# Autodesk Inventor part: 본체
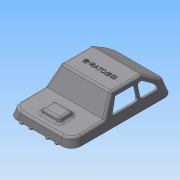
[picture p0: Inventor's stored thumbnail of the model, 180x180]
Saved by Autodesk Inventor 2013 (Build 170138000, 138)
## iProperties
Created: 2015-05
Part Number: 본체
Material: 일반
Document SubType Name: Modeling
Designer: dgall
Density: 1 g/cm^3
Author: dgall
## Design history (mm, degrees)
sketch "스케치1"
  geometry: L1 (-61, 0)-(-58.588, 9); L2 (-58.588, 9)-(-19, 10); L3 (-19, 10)-(-5.736, 30); L4 (-5.736, 30)-(31, 30); L5 (31, 30)-(61, 10); L6 (61, 10)-(61, 0); L7 (61, 0)-(-61, 0); 2 further points
  constraints: 14 end point, 1 coincident, 1 horizontal, 1 midpoint, 1 parallel, 1 vertical
  dimensions: "d0" = 122 distance of L6.end L1.start; "d1" = 9 vertical distance of L1.start L1.end; "d2" = 42 horizontal distance of L2.end L1.start; "d3" = 105 deg angle of L1 L7; "d4" = 30 distance between parallel lines of L7 L4; "d7" = 125 deg angle of L3 L2; "d8" = 20 vertical distance of L2.end L3.end; "d29" = 30 horizontal distance of L6.end L4.end; "d30" = 20 vertical distance of L5.end L4.end
extrude "돌출1" new body sketch "스케치1" stored distance "d10" = 76; taper "d11" = 0 deg
node "작업 평면1"
sketch "스케치2"
  geometry: L1 (38, 10)-(38, 30) reference; L2 (38, 9)-(38, 10) reference; L3 (38, 0)-(38, 9) reference; L4 (38, 0)-(-38, 0) reference; L5 (-38, 30)-(38, 30) reference; L6 (38, 0)-(29.962, 30); L7 (38, 0)-(38, 30); L8 (29.962, 30)-(38, 30); 1 further point
  constraints: 6 end point, 1 collinear, 1 perpendicular, 1 point on line
  dimensions: "d13" = 105 deg angle of L4 L6
extrude "돌출2" cut sketch "스케치2" distance "d14" = 150; taper "d15" = 0 deg
node "작업 평면2"
sketch "스케치4"
  geometry: L1 (61, 10)-(61, 0) reference; L2 (-61, 0)-(61, 0) reference; L3 (31, 30)-(61, 10) reference; L4 (61, 0)-(57.738, 12.175); L5 (57.738, 12.175)-(61, 10); L6 (61, 0)-(61, 10); 1 further point
  constraints: 6 end point, 1 collinear, 1 perpendicular, 1 point on line
  dimensions: "d32" = 105 deg angle of L4 L2
extrude "돌출3" cut sketch "스케치4" distance "d33" = 150; taper "d34" = 0 deg
feature "쉘2" dims "d35" = 2
sketch "스케치6"
  geometry: L1 (-5.736, 30)-(31, 30) reference; L2 (-19, 10)-(-5.736, 30) reference; L3 (31, 30)-(57.738, 12.175) reference; L4 (61, 0)-(57.738, 12.175) reference; L5 (-3.052, 25)-(-13, 10); L6 (-3.052, 25)-(21, 25); L7 (21, 25)-(21, 10); L8 (21, 10)-(-13, 10); L9 (29.486, 25)-(51.986, 10); L10 (29.486, 25)-(23.986, 25); L11 (23.986, 25)-(23.986, 10); L12 (23.986, 10)-(51.986, 10); 1 further point
  constraints: 16 end point, 6 parallel, 2 perpendicular
  dimensions: "d46" = 5 distance between parallel lines of L2 L5; "d48" = 5 distance between parallel lines of L1 L6; "d49" = 34 distance of L7.end L5.end; "d50" = 15 distance of L6.end L7.end; "d51" = 5 distance between parallel lines of L3 L9; "d52" = 5 distance from line of L1 L9.start; "d53" = 15 vertical distance of L9.start L9.end; "d54" = 28 distance of L11.end L9.end
extrude "돌출4" cut sketch "스케치6" distance "d55" = 150; taper "d56" = 0 deg
sketch "스케치8"
  geometry: L1 (0, 0)-(68.087, 0) reference; L2 (21.044, 26.867)-(47.044, 26.867); L3 (47.044, 26.867)-(47.044, 6.867); L4 (47.044, 6.867)-(21.044, 6.867); L5 (21.044, 6.867)-(21.044, 26.867); L6 (72.044, -4.133)-(-3.956, -4.133) reference; 3 further points
  constraints: 8 end point, 2 midpoint, 2 parallel, 1 horizontal, 1 perpendicular, 1 vertical alignment
  dimensions: "d63" = 26 distance of L2.start L2.end; "d65" = 20 distance of L2.end L3.end; "d66" = 11 distance between parallel lines of L4 L6
extrude "돌출6" join sketch "스케치8" distance "d67" = 7; taper "d68" = -20 deg
sketch "스케치9"
  geometry: L1 (21.044, 26.867)-(47.044, 26.867) reference; L2 (21.044, 6.867)-(21.044, 26.867) reference; L3 (47.044, 6.867)-(21.044, 6.867) reference; L4 (47.044, 26.867)-(47.044, 6.867) reference; L5 (45.044, 24.867)-(23.044, 24.867); L6 (23.044, 24.867)-(23.044, 8.867); L7 (23.044, 8.867)-(45.044, 8.867); L8 (45.044, 8.867)-(45.044, 24.867); 1 further point
  constraints: 8 end point, 3 other
  dimensions: "d69" = 2 distance between parallel lines of L1 L5
extrude "돌출7" cut sketch "스케치9" distance "d70" = 5; taper "d71" = -20 deg
fillet "모깎기1" dims "d72" = 12
fillet "모깎기2" dims "d73" = 12
fillet "모깎기3" dims "d74" = 3
fillet "모깎기4" dims "d75" = 3
fillet "모깎기5" dims "d76" = 3
fillet "모깎기6" dims "d77" = 3
sketch "스케치10"
  geometry: L1 (2.071, 119.929)-(50.747, 119.929) reference; L2 (62.338, 108.338)-(62.338, 13.662) reference; L3 (50.747, 2.071)-(2.071, 2.071) reference; L4 (-9.521, 13.662)-(-9.521, 108.338) reference; L5 (50.747, 120.929)-(2.071, 120.929); L6 (-10.521, 108.338)-(-10.521, 13.662); L7 (2.071, 1.071)-(50.747, 1.071); L8 (63.338, 13.662)-(63.338, 108.338); 5 further points; 4 other entities
  constraints: 8 end point, 7 parallel, 16 other
  dimensions: "d78" = 1 distance between parallel lines of L5 L1
extrude "돌출8" join sketch "스케치10" distance "d79" = 1; taper "d80" = 0 deg
fillet "모깎기7" dims "d81" = 3
sketch "스케치11"
  geometry: L1 (0, 122)-(52.818, 122) reference; C1 r 3 at (26.409, 21); 1 further point
  constraints: 1 centre point, 1 vertical alignment
  dimensions: "d82" = 6 diameter of C1; "d84" = 101 distance from line of L1 C1.centre
extrude "돌출9" join sketch "스케치11" stored distance "d85" = 1; taper "d86" = 2 deg
sketch "스케치12"
  geometry: L1 (-28.863, 9.751)-(-19, 10) reference; L2 (-19, 10)-(-6.626, 28.658) reference; L3 (-4.125, 30)-(30.092, 30) reference; L4 (31.756, 29.496)-(56.797, 12.802) reference; L5 (58.03, 11.082)-(61, 0) reference; L6 (61, 0)-(59.929, 0) reference; L7 (59.929, 0)-(59.929, -1) reference; L8 (59.929, -1)-(58.929, -1) reference; L9 (58.929, -1)-(58.929, 0) reference; L10 (58.929, 0)-(56.294, 9.837) reference; L11 (55.06, 11.556)-(31.15, 27.496) reference; L12 (29.486, 28)-(-3.052, 28) reference; L13 (-5.552, 26.658)-(-17.046, 9.328) reference; L14 (-19.47, 7.987)-(-30.084, 7.719) reference; L15 (-32.952, 9.621)-(-33.362, 10.664) reference; L16 (-36.23, 12.566)-(-36.561, 12.557) reference; L17 (-36.561, 12.557)-(-37, 0) reference; L18 (-37, 0)-(-43, 0) reference; L19 (-43, 0)-(-43.432, 12.384) reference; L20 (-43.432, 12.384)-(-44.386, 12.36) reference; L21 (-47.155, 10.315)-(-47.511, 9.254) reference; L22 (-50.279, 7.209)-(-54.802, 7.095) reference; L23 (-57.624, 4.872)-(-58.929, 0) reference; L24 (-58.929, 0)-(-58.929, -1) reference; L25 (-58.929, -1)-(-59.929, -1) reference; L26 (-59.929, -1)-(-59.929, 0) reference; L27 (-59.929, 0)-(-61, 0) reference; L28 (-61, 0)-(-59.169, 6.834) reference; L29 (-56.347, 9.057)-(-51.601, 9.176) reference; L30 (-48.833, 11.221)-(-48.477, 12.282) reference; L31 (-45.708, 14.327)-(-35.009, 14.597) reference; L32 (-32.141, 12.695)-(-31.731, 11.653) reference; L33 (-42.07, 2)-(-42.07, 12.919); L34 (-46.925, 12.919)-(-45, 2); L35 (47.338, 0)-(-47.338, 0) reference; L36 (-37, 0)-(-43, 0) reference; L37 (-45, 2)-(-42.07, 2); L38 (-42.07, 12.919)-(-46.925, 12.919); A1 r 3 centre (-28.939, 12.75) between (-31.731, 11.653) and (-28.863, 9.751) reference; A2 r 3 centre (-4.125, 27) between (-4.125, 30) and (-6.626, 28.658) reference; A3 r 3 centre (30.092, 27) between (31.756, 29.496) and (30.092, 30) reference; A4 r 3 centre (55.133, 10.306) between (58.03, 11.082) and (56.797, 12.802) reference; A5 r 3 centre (53.396, 9.06) between (56.294, 9.837) and (55.06, 11.556) reference; A6 r 3 centre (29.486, 25) between (31.15, 27.496) and (29.486, 28) reference; A7 r 3 centre (-3.052, 25) between (-3.052, 28) and (-5.552, 26.658) reference; A8 r 3 centre (-19.546, 10.987) between (-19.47, 7.987) and (-17.046, 9.328) reference; A9 r 3 centre (-30.16, 10.718) between (-32.952, 9.621) and (-30.084, 7.719) reference; A10 r 3 centre (-36.154, 9.567) between (-33.362, 10.664) and (-36.23, 12.566) reference; A11 r 3 centre (-44.311, 9.361) between (-44.386, 12.36) and (-47.155, 10.315) reference; A12 r 3 centre (-50.355, 10.208) between (-50.279, 7.209) and (-47.511, 9.254) reference; A13 r 3 centre (-54.726, 4.096) between (-54.802, 7.095) and (-57.624, 4.872) reference; A14 r 3 centre (-56.271, 6.058) between (-56.347, 9.057) and (-59.169, 6.834) reference; A15 r 3 centre (-51.677, 12.176) between (-51.601, 9.176) and (-48.833, 11.221) reference; A16 r 3 centre (-45.633, 11.328) between (-45.708, 14.327) and (-48.477, 12.282) reference; A17 r 3 centre (-34.933, 11.598) between (-32.141, 12.695) and (-35.009, 14.597) reference; 3 further points
  constraints: 8 end point, 2 parallel, 1 midpoint, 1 perpendicular, 1 point on circle, 1 point on line
  dimensions: "d90" = 10 deg angle of L33 L34; "d110" = 5 horizontal distance of point (-40, 0) L34.end; "d112" = 2.06984 distance from line of point (-40, 0) L33; "d114" = 2 distance between parallel lines of L35 L37; "d115" = 12.91909 distance between parallel lines of L36 L38
extrude "돌출10" join sketch "스케치12" stored distance "d92" = 2; taper "d93" = 0 deg
node "작업 평면3"
hole "구멍1" diameter "d97" = 3.242; stored, may be unused: countersink angle "d101" = 90 deg, drill point angle "d103" = 118 deg; dims "d95" = 10, "d96" = 10, "d98" = 9, "d99" = 4, "d100" = 2, "d102" = 11
sketch "스케치13"
  geometry: C1 r 3 at (26.409, 101); C2 r 1.621 at (26.409, 21) reference; 1 further point
  constraints: 1 centre point, 1 vertical alignment
  dimensions: "d104" = 6 diameter of C1; "d106" = 80 distance of C1.centre C2.centre
extrude "돌출11" join sketch "스케치13" stored distance "d107" = 2; taper "d108" = 2 deg
sketch "스케치14"
  geometry: L1 (-28.863, 9.751)-(-19, 10) reference; L2 (-19, 10)-(-6.626, 28.658) reference; L3 (-4.125, 30)-(30.092, 30) reference; L4 (31.756, 29.496)-(56.797, 12.802) reference; L5 (58.03, 11.082)-(61, 0) reference; L6 (61, 0)-(59.929, 0) reference; L7 (59.929, 0)-(59.929, -1) reference; L8 (59.929, -1)-(58.929, -1) reference; L9 (58.929, -1)-(58.929, 0) reference; L10 (58.929, 0)-(56.294, 9.837) reference; L11 (55.06, 11.556)-(43.669, 19.15) reference; L12 (43.669, 19.15)-(43, 0) reference; L13 (43, 0)-(37, 0) reference; L14 (37, 0)-(36.156, 24.159) reference; L15 (36.156, 24.159)-(31.15, 27.496) reference; L16 (29.486, 28)-(-3.052, 28) reference; L17 (-5.552, 26.658)-(-17.046, 9.328) reference; L18 (-19.47, 7.987)-(-30.084, 7.719) reference; L19 (-32.952, 9.621)-(-33.362, 10.664) reference; L20 (-33.44, 10.845)-(-35, 2) reference; L21 (-36.93, 2)-(-37, 0) reference; L22 (-37, 0)-(-38.379, 0) reference; L23 (-38.379, 0)-(-38.379, 11) reference; L24 (-38.379, 11)-(-40, 11.974) reference; L25 (-40, 11.974)-(-41.621, 11) reference; L26 (-41.621, 11)-(-41.621, 0) reference; L27 (-41.621, 0)-(-43, 0) reference; L28 (-43, 0)-(-43.07, 2) reference; L29 (-45, 2)-(-46.633, 11.26) reference; L30 (-47.155, 10.315)-(-47.511, 9.254) reference; L31 (-50.279, 7.209)-(-54.802, 7.095) reference; L32 (-57.624, 4.872)-(-58.929, 0) reference; L33 (-58.929, 0)-(-58.929, -1) reference; L34 (-58.929, -1)-(-59.929, -1) reference; L35 (-59.929, -1)-(-59.929, 0) reference; L36 (-59.929, 0)-(-61, 0) reference; L37 (-61, 0)-(-59.169, 6.834) reference; L38 (-56.347, 9.057)-(-51.601, 9.176) reference; L39 (-48.833, 11.221)-(-48.477, 12.282) reference; L40 (-45.708, 14.327)-(-35.009, 14.597) reference; L41 (-32.141, 12.695)-(-31.731, 11.653) reference; L42 (-35, 2)-(-36.93, 2) reference; L43 (-43.07, 2)-(-45, 2) reference; L44 (43, 0)-(46.092, 17.535); L45 (37, 0)-(32.285, 26.74); L46 (40, 0)-(40, 24); L47 (37, 0)-(38.023, 0); L48 (38.023, 0)-(38.023, 23.037); L49 (38.023, 23.037)-(36.156, 24.159); L50 (43, 0)-(42.333, 0); L51 (42.333, 0)-(42.333, 19.953); L52 (42.333, 19.953)-(43.669, 19.15); A1 r 3 centre (-28.939, 12.75) between (-31.731, 11.653) and (-28.863, 9.751) reference; A2 r 3 centre (-4.125, 27) between (-4.125, 30) and (-6.626, 28.658) reference; A3 r 3 centre (30.092, 27) between (31.756, 29.496) and (30.092, 30) reference; A4 r 3 centre (55.133, 10.306) between (58.03, 11.082) and (56.797, 12.802) reference; A5 r 3 centre (53.396, 9.06) between (56.294, 9.837) and (55.06, 11.556) reference; A6 r 3 centre (29.486, 25) between (31.15, 27.496) and (29.486, 28) reference; A7 r 3 centre (-3.052, 25) between (-3.052, 28) and (-5.552, 26.658) reference; A8 r 3 centre (-19.546, 10.987) between (-19.47, 7.987) and (-17.046, 9.328) reference; A9 r 3 centre (-30.16, 10.718) between (-32.952, 9.621) and (-30.084, 7.719) reference; A10 r 3 centre (-36.154, 9.567) between (-33.362, 10.664) and (-33.44, 10.845) reference; A11 r 3 centre (-44.311, 9.361) between (-46.633, 11.26) and (-47.155, 10.315) reference; A12 r 3 centre (-50.355, 10.208) between (-50.279, 7.209) and (-47.511, 9.254) reference; A13 r 3 centre (-54.726, 4.096) between (-54.802, 7.095) and (-57.624, 4.872) reference; A14 r 3 centre (-56.271, 6.058) between (-56.347, 9.057) and (-59.169, 6.834) reference; A15 r 3 centre (-51.677, 12.176) between (-51.601, 9.176) and (-48.833, 11.221) reference; A16 r 3 centre (-45.633, 11.328) between (-45.708, 14.327) and (-48.477, 12.282) reference; A17 r 3 centre (-34.933, 11.598) between (-32.141, 12.695) and (-35.009, 14.597) reference; 1 further point
  constraints: 18 end point, 5 point on line, 3 perpendicular, 2 parallel, 1 midpoint
  dimensions: "d116" = 10 deg angle of L46 L45; "d117" = 10 deg angle of L46 L44
extrude "돌출12" join sketch "스케치14" stored distance "d118" = 2; taper "d119" = 0 deg
hole "구멍2" diameter "d122" = 3.242; stored, may be unused: countersink angle "d126" = 90 deg, drill point angle "d128" = 118 deg; dims "d120" = 10, "d121" = 10, "d123" = 9, "d124" = 4, "d125" = 2, "d127" = 11
sketch "스케치15"
  geometry: C1 r 3 at (48.12, 61.012); C2 r 1.621 at (26.12, 101.012) reference; 1 further point
  constraints: 1 centre point
  dimensions: "d129" = 6 diameter of C1; "d131" = 40 vertical distance of C2.centre C1.centre; "d132" = 22 horizontal distance of C2.centre C1.centre
extrude "돌출13" join sketch "스케치15" stored distance "d133" = 2; taper "d134" = 2 deg
node "작업 평면4"
sketch "스케치16"
  geometry: L1 (-56.347, 9.057)-(-19, 10) reference; L2 (-19, 10)-(-6.626, 28.658) reference; L3 (-4.125, 30)-(30.092, 30) reference; L4 (31.756, 29.496)-(56.797, 12.802) reference; L5 (58.03, 11.082)-(61, 0) reference; L6 (61, 0)-(59.929, 0) reference; L7 (59.929, 0)-(59.929, -1) reference; L8 (59.929, -1)-(58.929, -1) reference; L9 (58.929, -1)-(58.929, 0) reference; L10 (58.929, 0)-(56.591, 8.727) reference; L11 (55.054, 11.56)-(31.15, 27.496) reference; L12 (29.486, 28)-(3.979, 28) reference; L13 (2.998, 0)-(-2.974, 0) reference; L14 (-5.552, 26.658)-(-17.046, 9.328) reference; L15 (-19.47, 7.987)-(-54.802, 7.095) reference; L16 (-57.624, 4.872)-(-58.929, 0) reference; L17 (-58.929, 0)-(-58.929, -1) reference; L18 (-58.929, -1)-(-59.929, -1) reference; L19 (-59.929, -1)-(-59.929, 0) reference; L20 (-59.929, 0)-(-61, 0) reference; L21 (-61, 0)-(-59.169, 6.834) reference; L22 (-2.974, 0)-(-7.402, 25.113); L23 (2.998, 0)-(7.93, 27.969); L24 (0, 0)-(0, 30); L25 (-7.402, 25.113)-(-5.508, 27.969); L26 (-5.508, 27.969)-(-2, 27.969); L27 (-2.974, 0)-(-2, 0); L28 (-2, 0)-(-2, 28); L29 (2.998, 0)-(1.601, 0); L30 (1.601, 0)-(1.601, 27.969); L31 (1.601, 27.969)-(7.93, 27.969); A1 r 3 centre (-56.271, 6.058) between (-56.347, 9.057) and (-59.169, 6.834) reference; A2 r 3 centre (-4.125, 27) between (-4.125, 30) and (-6.626, 28.658) reference; A3 r 3 centre (30.092, 27) between (31.756, 29.496) and (30.092, 30) reference; A4 r 3 centre (55.133, 10.306) between (58.03, 11.082) and (56.797, 12.802) reference; A5 r 3 centre (29.486, 25) between (31.15, 27.496) and (29.486, 28) reference; A6 r 3 centre (-3.052, 25) between (-3.95, 27.862) and (-5.552, 26.658) reference; A7 r 3 centre (-19.546, 10.987) between (-19.47, 7.987) and (-17.046, 9.328) reference; A8 r 3 centre (-54.726, 4.096) between (-54.802, 7.095) and (-57.624, 4.872) reference; 2 further points; 1 other entity
  constraints: 20 end point, 5 perpendicular, 4 point on line, 2 parallel, 1 horizontal alignment, 4 other
  dimensions: "d136" = 10 deg angle of L24 L22; "d137" = 10 deg angle of L23 L24
extrude "돌출14" join sketch "스케치16" stored distance "d138" = 2; taper "d139" = 0 deg
hole "구멍3" diameter "d142" = 3.242; stored, may be unused: countersink angle "d146" = 90 deg, drill point angle "d148" = 118 deg; dims "d140" = 10, "d141" = 10, "d143" = 9, "d144" = 4, "d145" = 2, "d147" = 11
sketch "스케치18"
  geometry: L1 (54.068, 65.125)-(1.251, 65.125) reference; 3 further points
  constraints: 1 midpoint, 1 vertical alignment, 1 other
  dimensions: "d149" = 50 distance from line of L1 point (27.66, 15.125)
feature "엠보싱1" sketch "스케치18" dims "d150" = 0.5, "d151" = 0
node "작업 평면5"
sketch "스케치19"
  geometry: L1 (-2.071, 0)-(50.747, 0) reference; A1 r 2 centre (14.338, 0) between (16.338, 0) and (12.338, 0); A2 r 2 centre (3.338, 0) between (5.338, 0) and (1.338, 0); 1 further point
  constraints: 4 point on circle, 4 point on line, 2 centre point, 2 horizontal alignment, 1 equal radius
  dimensions: "d155" = 4 diameter of A1; "d157" = 10 distance of point (24.338, 0) A1.centre; "d158" = 11 distance of A1.centre A2.centre
extrude "돌출15" join sketch "스케치19" stored distance "d159" = 2; taper "d160" = 0 deg
chamfer "모따기1" distance "d161" = 1; stored, may be unused: second distance "d162" = 2, angle "d163" = 45 deg
node "솔리드1"
mirror "대칭1"
mirror "대칭2"
mirror "대칭3"
mirror "대칭4"
node "절단 모서리 투영1"
node "절단 모서리 투영2"
node "절단 모서리 투영3"
other parameters: "d31" = 51.75, "d135" = -22, "d152" = 3
